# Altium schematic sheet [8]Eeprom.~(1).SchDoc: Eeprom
size A4; Organization: BQR; Address1: Reliability Engineering; Address2: Optimized Maintenance; Address3: www.bqr.com; Address4: www.bqr-digital.com; DocumentNumber: DOC9; SheetNumber: 5; SheetTotal: 13
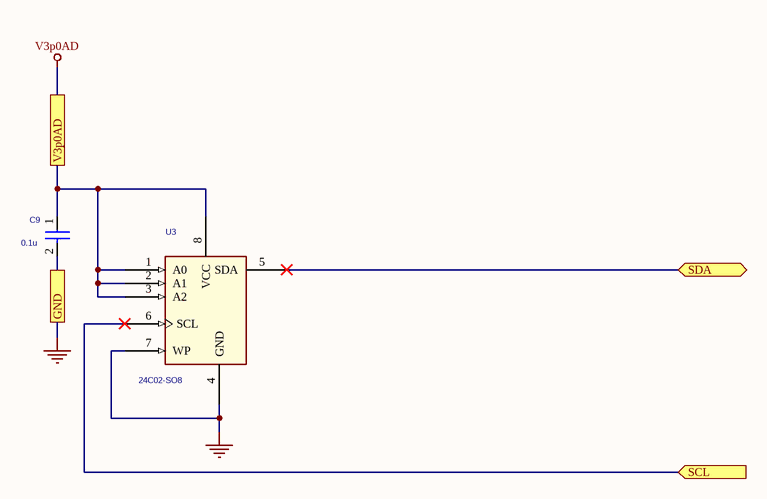
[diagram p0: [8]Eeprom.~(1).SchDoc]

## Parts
C9  0.1u  [0603]
U3  24C02-SO8  [soic8_150amps]

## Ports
GND, SCL (in), SDA (bidir), V3p0AD

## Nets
GND: C9.2 U3.4(GND) U3.7(WP) ; port GND
V3p0AD: C9.1 U3.1(A0) U3.2(A1) U3.3(A2) U3.8(VCC) ; port V3p0AD
SCL: U3.6(SCL) ; port SCL
SDA: U3.5(SDA) ; port SDA

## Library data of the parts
C9 = Capacitor_4: CAP CER 0.1UF 16V X7R 0603; Manufacturer: Murata; Manufacturer P/N: GRM188R71C104KA01D; Catalog Number: CAP00036; SDTA_V(Voltage): 3; fiX_Func: EEPROM (8)
U3 = 24C02-SO8_2: EEPROM 2/4/8/16K 2-WIRE BUS; Manufacturer: Atmel; Manufacturer P/N: AT24C02AN-10SU-2.7; fiX_Manuf: Fairchild; Catalog Number: IC00009; fiX_Func: EEPROM (8)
